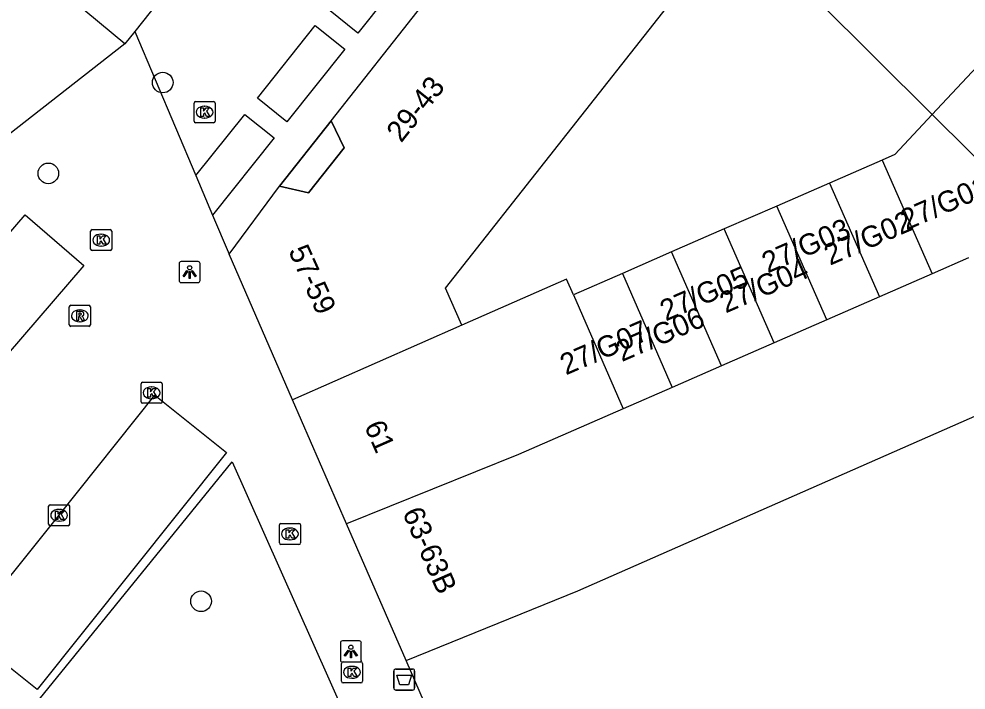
# Model space of a CAD drawing. Extents: x 161882 to 162509, y 381687 to 382379.
# Drawn here: x 162060.59 to 162105.57, y 382010.81 to 382042.68 of the extents above; entities that cross this region are included whole.
import ezdxf

# ---------------------------------------------------------------- set-up
doc = ezdxf.new("R2010")
doc.units = 0
for name, color, linetype in [('IMGEO_Afvalbak', 7, 'Continuous'), ('IMGEO_Boom', 7, 'Continuous'), ('IMGEO_Kolk', 7, 'Continuous'), ('IMGEO_Lichtpunt', 7, 'Continuous'), ('IMGEO_Muur', 7, 'Continuous'), ('IMGEO_Pand', 7, 'Continuous'), ('IMGEO_Pand_nummerreeks', 7, 'Continuous'), ('IMGEO_Pand_overbouw', 7, 'Continuous'), ('IMGEO_Parkeervlak_open', 7, 'Continuous'), ('IMGEO_Rioolput', 7, 'Continuous'), ('IMGEO_Voetpad_open', 7, 'Continuous')]:
    doc.layers.add(name, color=color, linetype=linetype)

msp = doc.modelspace()

# ---------------------------------------------------------------- linework, layer by layer
at = {"layer": 'IMGEO_Afvalbak'}
for p, q in [((162078.395, 382010.911), (162078.395, 382011.711)), ((162078.395, 382011.711), (162078.395, 382010.911)), ((162078.495, 382011.811), (162079.285, 382011.811)), ((162079.285, 382011.811), (162078.495, 382011.811)), ((162079.385, 382011.711), (162079.385, 382010.911)), ((162079.385, 382010.911), (162079.385, 382011.711)), ((162079.285, 382010.811), (162078.495, 382010.811)), ((162078.495, 382010.811), (162079.285, 382010.811))]:
    msp.add_line(p, q, dxfattribs=at)
msp.add_lwpolyline([(162078.538, 382011.525), (162079.242, 382011.525), (162079.093, 382011.055), (162078.687, 382011.055), (162078.538, 382011.525)], dxfattribs=at)
for centre, start, end in [((162078.495, 382011.711), 90, 180), ((162078.495, 382011.711), 90, 180), ((162079.285, 382011.711), 0, 90), ((162079.285, 382011.711), 360, 90), ((162078.495, 382010.911), 180, 270), ((162078.495, 382010.911), 180, 270), ((162079.285, 382010.911), 270, 0), ((162079.285, 382010.911), 270, 0)]:
    msp.add_arc(centre, 0.1, start, end, dxfattribs=at)
at = {"layer": 'IMGEO_Boom'}
for centre in [(162067.42, 382039.66), (162061.986, 382035.347), (162069.241, 382015.027)]:
    msp.add_circle(centre, 0.489, dxfattribs=at)
at = {"layer": 'IMGEO_Kolk'}
for p, q in [((162068.907, 382037.829), (162068.907, 382038.681)), ((162068.982, 382038.755), (162069.834, 382038.755)), ((162069.395, 382038.535), (162069.42, 382038.535)), ((162069.908, 382038.681), (162069.908, 382037.829)), ((162069.418, 382037.975), (162069.393, 382037.975)), ((162069.834, 382037.755), (162068.982, 382037.755)), ((162063.995, 382031.752), (162063.995, 382032.604)), ((162064.07, 382032.678), (162064.922, 382032.678)), ((162064.996, 382032.604), (162064.996, 382031.752)), ((162064.483, 382032.458), (162064.508, 382032.458)), ((162064.922, 382031.678), (162064.07, 382031.678)), ((162064.506, 382031.898), (162064.481, 382031.898)), ((162066.465, 382025.428), (162067.317, 382025.428)), ((162066.39, 382024.502), (162066.39, 382025.354)), ((162066.878, 382025.208), (162066.903, 382025.208)), ((162067.391, 382025.354), (162067.391, 382024.502)), ((162066.901, 382024.648), (162066.876, 382024.648)), ((162067.317, 382024.428), (162066.465, 382024.428)), ((162061.998, 382018.686), (162061.998, 382019.538)), ((162062.073, 382019.612), (162062.925, 382019.612)), ((162062.999, 382019.538), (162062.999, 382018.686)), ((162062.486, 382019.392), (162062.511, 382019.392)), ((162062.509, 382018.832), (162062.484, 382018.832)), ((162072.96, 382017.799), (162072.96, 382018.651)), ((162073.035, 382018.725), (162073.887, 382018.725)), ((162073.961, 382018.651), (162073.961, 382017.799)), ((162062.925, 382018.612), (162062.073, 382018.612)), ((162073.448, 382018.505), (162073.473, 382018.505)), ((162073.471, 382017.945), (162073.446, 382017.945)), ((162073.887, 382017.725), (162073.035, 382017.725)), ((162075.907, 382011.228), (162075.907, 382012.08)), ((162075.982, 382012.154), (162076.834, 382012.154)), ((162076.395, 382011.934), (162076.42, 382011.934)), ((162076.908, 382012.08), (162076.908, 382011.228)), ((162076.834, 382011.154), (162075.982, 382011.154)), ((162076.418, 382011.374), (162076.393, 382011.374))]:
    msp.add_line(p, q, dxfattribs=at)
for points in [[(162068.907, 382037.829), (162068.907, 382038.681)], [(162068.982, 382038.755), (162069.834, 382038.755)], [(162069.228, 382038.455), (162069.351, 382038.455), (162069.351, 382038.304), (162069.481, 382038.455), (162069.645, 382038.455), (162069.499, 382038.304), (162069.652, 382038.055), (162069.5, 382038.055), (162069.415, 382038.219), (162069.351, 382038.152), (162069.351, 382038.055), (162069.228, 382038.055), (162069.228, 382038.455)], [(162069.908, 382038.681), (162069.908, 382037.829)], [(162069.834, 382037.755), (162068.982, 382037.755)], [(162063.995, 382031.752), (162063.995, 382032.604)], [(162064.07, 382032.678), (162064.922, 382032.678)], [(162064.996, 382032.604), (162064.996, 382031.752)], [(162064.316, 382032.378), (162064.439, 382032.378), (162064.439, 382032.227), (162064.569, 382032.378), (162064.733, 382032.378), (162064.587, 382032.227), (162064.74, 382031.978), (162064.588, 382031.978), (162064.503, 382032.142), (162064.439, 382032.075), (162064.439, 382031.978), (162064.316, 382031.978), (162064.316, 382032.378)], [(162064.922, 382031.678), (162064.07, 382031.678)], [(162066.465, 382025.428), (162067.317, 382025.428)], [(162066.39, 382024.502), (162066.39, 382025.354)], [(162066.711, 382025.128), (162066.834, 382025.128), (162066.834, 382024.977), (162066.964, 382025.128), (162067.128, 382025.128), (162066.982, 382024.977), (162067.135, 382024.728), (162066.983, 382024.728), (162066.898, 382024.892), (162066.834, 382024.825), (162066.834, 382024.728), (162066.711, 382024.728), (162066.711, 382025.128)], [(162067.391, 382025.354), (162067.391, 382024.502)], [(162067.317, 382024.428), (162066.465, 382024.428)], [(162061.998, 382018.686), (162061.998, 382019.538)], [(162062.073, 382019.612), (162062.925, 382019.612)], [(162062.999, 382019.538), (162062.999, 382018.686)], [(162062.319, 382019.312), (162062.442, 382019.312), (162062.442, 382019.161), (162062.572, 382019.312), (162062.736, 382019.312), (162062.59, 382019.161), (162062.743, 382018.912), (162062.591, 382018.912), (162062.506, 382019.076), (162062.442, 382019.009), (162062.442, 382018.912), (162062.319, 382018.912), (162062.319, 382019.312)], [(162072.96, 382017.799), (162072.96, 382018.651)], [(162073.035, 382018.725), (162073.887, 382018.725)], [(162073.961, 382018.651), (162073.961, 382017.799)], [(162062.925, 382018.612), (162062.073, 382018.612)], [(162073.281, 382018.425), (162073.404, 382018.425), (162073.404, 382018.274), (162073.534, 382018.425), (162073.698, 382018.425), (162073.552, 382018.274), (162073.705, 382018.025), (162073.553, 382018.025), (162073.468, 382018.189), (162073.404, 382018.122), (162073.404, 382018.025), (162073.281, 382018.025), (162073.281, 382018.425)], [(162073.887, 382017.725), (162073.035, 382017.725)], [(162075.907, 382011.228), (162075.907, 382012.08)], [(162075.982, 382012.154), (162076.834, 382012.154)], [(162076.908, 382012.08), (162076.908, 382011.228)], [(162076.228, 382011.854), (162076.351, 382011.854), (162076.351, 382011.703), (162076.481, 382011.854), (162076.645, 382011.854), (162076.499, 382011.703), (162076.652, 382011.454), (162076.5, 382011.454), (162076.415, 382011.618), (162076.351, 382011.551), (162076.351, 382011.454), (162076.228, 382011.454), (162076.228, 382011.854)], [(162076.834, 382011.154), (162075.982, 382011.154)]]:
    msp.add_lwpolyline(points, dxfattribs=at)
for centre, start, end in [((162068.984, 382038.679), 91.552, 178.448), ((162068.984, 382038.679), 91.552, 178.448), ((162069.832, 382038.679), 1.552, 88.448), ((162069.832, 382038.679), 1.552, 88.448), ((162068.984, 382037.831), 181.552, 268.448), ((162068.984, 382037.831), 181.552, 268.448), ((162069.832, 382037.831), 271.552, 358.448), ((162069.832, 382037.831), 271.552, 358.448), ((162064.072, 382032.602), 91.552, 178.448), ((162064.072, 382032.602), 91.552, 178.448), ((162064.92, 382032.602), 1.552, 88.448), ((162064.92, 382032.602), 1.552, 88.448), ((162064.072, 382031.754), 181.552, 268.448), ((162064.072, 382031.754), 181.552, 268.448), ((162064.92, 382031.754), 271.552, 358.448), ((162064.92, 382031.754), 271.552, 358.448), ((162066.467, 382025.352), 91.552, 178.448), ((162066.467, 382025.352), 91.552, 178.448), ((162067.315, 382025.352), 1.552, 88.448), ((162067.315, 382025.352), 1.552, 88.448), ((162066.467, 382024.504), 181.552, 268.448), ((162066.467, 382024.504), 181.552, 268.448), ((162067.315, 382024.504), 271.552, 358.448), ((162067.315, 382024.504), 271.552, 358.448), ((162062.075, 382019.536), 91.552, 178.448), ((162062.075, 382019.536), 91.552, 178.448), ((162062.923, 382019.536), 1.552, 88.448), ((162062.923, 382019.536), 1.552, 88.448), ((162062.075, 382018.688), 181.552, 268.448), ((162062.075, 382018.688), 181.552, 268.448), ((162062.923, 382018.688), 271.552, 358.448), ((162062.923, 382018.688), 271.552, 358.448), ((162073.037, 382018.649), 91.552, 178.448), ((162073.037, 382018.649), 91.552, 178.448), ((162073.885, 382018.649), 1.552, 88.448), ((162073.885, 382018.649), 1.552, 88.448), ((162073.037, 382017.801), 181.552, 268.448), ((162073.037, 382017.801), 181.552, 268.448), ((162073.885, 382017.801), 271.552, 358.448), ((162073.885, 382017.801), 271.552, 358.448), ((162075.984, 382012.078), 91.552, 178.448), ((162075.984, 382012.078), 91.552, 178.448), ((162076.832, 382012.078), 1.552, 88.448), ((162076.832, 382012.078), 1.552, 88.448), ((162075.984, 382011.23), 181.552, 268.448), ((162075.984, 382011.23), 181.552, 268.448), ((162076.832, 382011.23), 271.552, 358.448), ((162076.832, 382011.23), 271.552, 358.448)]:
    msp.add_arc(centre, 0.0765, start, end, dxfattribs=at)
for centre, major_axis, ratio, start_param, end_param in [((162069.394, 382038.255), (-0.387, 0.002), 0.722429, 4.712389, 7.853982), ((162069.419, 382038.255), (-0.39, 0.002), 0.717154, 1.570796, 4.712389), ((162064.482, 382032.178), (-0.387, 0.002), 0.722429, 4.712389, 7.853982), ((162064.507, 382032.178), (-0.39, 0.002), 0.717154, 1.570796, 4.712389), ((162066.877, 382024.928), (-0.387, 0.002), 0.722429, 4.712389, 7.853982), ((162066.902, 382024.928), (-0.39, 0.002), 0.717154, 1.570796, 4.712389), ((162062.485, 382019.112), (-0.387, 0.002), 0.722429, 4.712389, 7.853982), ((162062.51, 382019.112), (-0.39, 0.002), 0.717154, 1.570796, 4.712389), ((162073.447, 382018.225), (-0.387, 0.002), 0.722429, 4.712389, 7.853982), ((162073.472, 382018.225), (-0.39, 0.002), 0.717154, 1.570796, 4.712389), ((162076.394, 382011.654), (-0.387, 0.002), 0.722429, 4.712389, 7.853982), ((162076.419, 382011.654), (-0.39, 0.002), 0.717154, 1.570796, 4.712389)]:
    msp.add_ellipse(centre, major_axis=major_axis, ratio=ratio, start_param=start_param, end_param=end_param, dxfattribs=at)
at = {"layer": 'IMGEO_Lichtpunt'}
for p, q in [((162068.197, 382031.066), (162068.197, 382030.259)), ((162068.197, 382031.066), (162068.197, 382030.259)), ((162069.099, 382031.161), (162068.291, 382031.161)), ((162069.099, 382031.161), (162068.291, 382031.161)), ((162069.193, 382030.259), (162069.193, 382031.066)), ((162069.193, 382030.259), (162069.193, 382031.066)), ((162068.291, 382030.165), (162069.099, 382030.165)), ((162068.291, 382030.165), (162069.099, 382030.165)), ((162075.856, 382013.048), (162075.856, 382012.241)), ((162075.856, 382013.048), (162075.856, 382012.241)), ((162076.758, 382013.143), (162075.95, 382013.143)), ((162076.758, 382013.143), (162075.95, 382013.143)), ((162076.852, 382012.241), (162076.852, 382013.048)), ((162076.852, 382012.241), (162076.852, 382013.048)), ((162075.95, 382012.147), (162076.758, 382012.147)), ((162075.95, 382012.147), (162076.758, 382012.147))]:
    msp.add_line(p, q, dxfattribs=at)
for points in [[(162068.571, 382030.73), (162068.61, 382030.702), (162068.422, 382030.44), (162068.384, 382030.467), (162068.571, 382030.73)], [(162068.673, 382030.682), (162068.72, 382030.682), (162068.72, 382030.36), (162068.673, 382030.36), (162068.673, 382030.682)], [(162068.783, 382030.702), (162068.821, 382030.729), (162069.008, 382030.467), (162068.969, 382030.439), (162068.783, 382030.702)], [(162076.23, 382012.712), (162076.269, 382012.684), (162076.081, 382012.422), (162076.043, 382012.449), (162076.23, 382012.712)], [(162076.332, 382012.664), (162076.379, 382012.664), (162076.379, 382012.342), (162076.332, 382012.342), (162076.332, 382012.664)], [(162076.442, 382012.684), (162076.48, 382012.711), (162076.667, 382012.449), (162076.628, 382012.421), (162076.442, 382012.684)]]:
    msp.add_lwpolyline(points, dxfattribs=at)
for centre in [(162068.696, 382030.864), (162076.355, 382012.846)]:
    msp.add_circle(centre, 0.0994, dxfattribs=at)
for centre, start, end in [((162068.291, 382031.066), 90, 180), ((162068.291, 382031.066), 90, 180), ((162069.099, 382031.066), 0, 90), ((162069.099, 382031.066), 0, 90), ((162068.291, 382030.259), 180, 270), ((162068.291, 382030.259), 180, 270), ((162069.099, 382030.259), 270, 0), ((162069.099, 382030.259), 270, 360), ((162075.95, 382013.048), 90, 180), ((162075.95, 382013.048), 90, 180), ((162076.758, 382013.048), 0, 90), ((162076.758, 382013.048), 0, 90), ((162075.95, 382012.241), 180, 270), ((162075.95, 382012.241), 180, 270), ((162076.758, 382012.241), 270, 0), ((162076.758, 382012.241), 270, 360)]:
    msp.add_arc(centre, 0.0946, start, end, dxfattribs=at)
at = {"layer": 'IMGEO_Muur'}
msp.add_lwpolyline([(162093.049, 382049.003), (162103.972, 382038.147)], dxfattribs=at)
at = {"layer": 'IMGEO_Pand'}
for points in [[(162065.624, 382041.496), (162054.951, 382050.341)], [(162069.304, 382046.153), (162066.089, 382042.085)], [(162081.622, 382028.142), (162080.853, 382029.902), (162091.578, 382043.507), (162089.962, 382044.781), (162090.783, 382045.823)], [(162075.416, 382037.845), (162079.747, 382043.318)], [(162066.089, 382042.085), (162065.624, 382041.496)], [(162103.972, 382038.147), (162107.753, 382042.178), (162112.396, 382037.564), (162111.772, 382036.656), (162112.254, 382036.261)], [(162065.624, 382041.496), (162047.564, 382027.394)], [(162103.972, 382038.147), (162102.186, 382036.243), (162101.589, 382035.982)], [(162109.264, 382032.889), (162103.972, 382038.147)], [(162075.416, 382037.845), (162076.035, 382036.565), (162074.335, 382034.416), (162072.958, 382034.74)], [(162101.589, 382035.982), (162099.082, 382034.888)], [(162101.589, 382035.982), (162103.968, 382030.577)], [(162099.082, 382034.888), (162096.583, 382033.797)], [(162099.082, 382034.888), (162101.461, 382029.482)], [(162070.577, 382031.503), (162072.958, 382034.74)], [(162096.583, 382033.797), (162094.084, 382032.706)], [(162098.962, 382028.391), (162096.583, 382033.797)], [(162094.084, 382032.706), (162091.585, 382031.615)], [(162096.464, 382027.3), (162094.084, 382032.706)], [(162073.588, 382024.593), (162070.577, 382031.503)], [(162091.585, 382031.615), (162089.255, 382030.597)], [(162093.965, 382026.209), (162091.585, 382031.615)], [(162105.694, 382031.331), (162103.968, 382030.577)], [(162089.255, 382030.597), (162086.925, 382029.58)], [(162089.255, 382030.597), (162091.618, 382025.184)], [(162103.968, 382030.577), (162101.461, 382029.482)], [(162086.925, 382029.58), (162086.603, 382030.317), (162081.622, 382028.142)], [(162086.925, 382029.58), (162089.288, 382024.167)], [(162101.461, 382029.482), (162098.962, 382028.391)], [(162081.622, 382028.142), (162073.588, 382024.593)], [(162098.962, 382028.391), (162096.464, 382027.3)], [(162096.464, 382027.3), (162093.965, 382026.209)], [(162093.965, 382026.209), (162091.618, 382025.184)], [(162078.98, 382012.213), (162087.135, 382015.525), (162108.51, 382024.928)], [(162091.618, 382025.184), (162089.288, 382024.167)], [(162076.155, 382018.699), (162073.588, 382024.593)], [(162089.288, 382024.167), (162084.309, 382021.993), (162076.155, 382018.699)], [(162078.98, 382012.213), (162076.155, 382018.699)], [(162081.094, 382007.361), (162078.98, 382012.213)]]:
    msp.add_lwpolyline(points, dxfattribs=at)
at = {"layer": 'IMGEO_Pand_overbouw'}
msp.add_lwpolyline([(162075.416, 382037.845), (162072.958, 382034.74), (162074.335, 382034.416), (162076.035, 382036.565)], close=True, dxfattribs=at)
at = {"layer": 'IMGEO_Parkeervlak_open'}
for points in [[(162093.049, 382049.003), (162103.972, 382038.147)], [(162079.441, 382045.475), (162076.68, 382042.013), (162075.285, 382043.128), (162078.037, 382046.607), (162079.441, 382045.475)], [(162076.074, 382041.241), (162073.317, 382037.797), (162071.919, 382038.914), (162074.663, 382042.368), (162076.074, 382041.241)], [(162068.992, 382035.24), (162071.32, 382038.151), (162072.716, 382037.039), (162069.789, 382033.361)]]:
    msp.add_lwpolyline(points, dxfattribs=at)
at = {"layer": 'IMGEO_Rioolput'}
for p, q in [((162062.981, 382028.158), (162062.981, 382029.01)), ((162063.056, 382029.084), (162063.908, 382029.084)), ((162063.982, 382029.01), (162063.982, 382028.158)), ((162063.469, 382028.864), (162063.494, 382028.864)), ((162063.908, 382028.084), (162063.056, 382028.084)), ((162063.492, 382028.304), (162063.467, 382028.304))]:
    msp.add_line(p, q, dxfattribs=at)
for points in [[(162062.981, 382028.158), (162062.981, 382029.01)], [(162063.056, 382029.084), (162063.908, 382029.084)], [(162063.982, 382029.01), (162063.982, 382028.158)], [(162063.57, 382028.782), (162063.318, 382028.784), (162063.318, 382028.384)], [(162063.318, 382028.384), (162063.442, 382028.384), (162063.442, 382028.546), (162063.453, 382028.546)], [(162063.496, 382028.703), (162063.442, 382028.703), (162063.442, 382028.622)], [(162063.442, 382028.622), (162063.494, 382028.622)], [(162063.908, 382028.084), (162063.056, 382028.084)], [(162063.5, 382028.517), (162063.571, 382028.384), (162063.711, 382028.384), (162063.646, 382028.51)]]:
    msp.add_lwpolyline(points, dxfattribs=at)
for centre, radius, start, end in [((162063.058, 382029.008), 0.0765, 91.552, 178.448), ((162063.058, 382029.008), 0.0765, 91.552, 178.448), ((162063.906, 382029.008), 0.0765, 1.552, 88.448), ((162063.906, 382029.008), 0.0765, 1.552, 88.448), ((162063.452, 382028.493), 0.0533, 26.0293, 88.6989), ((162063.478, 382028.811), 0.19, 274.7715, 282.9687), ((162063.502, 382028.607), 0.0964, 77.0061, 93.1865), ((162063.516, 382028.664), 0.0378, 276.6634, 79.6772), ((162063.569, 382028.672), 0.109, 350.3612, 89.416), ((162063.567, 382028.672), 0.112, 277.5842, 350.9817), ((162063.551, 382028.457), 0.108, 29.5134, 73.7905), ((162063.058, 382028.16), 0.0765, 181.552, 268.448), ((162063.058, 382028.16), 0.0765, 181.552, 268.448), ((162063.906, 382028.16), 0.0765, 271.552, 358.448), ((162063.906, 382028.16), 0.0765, 271.552, 358.448)]:
    msp.add_arc(centre, radius, start, end, dxfattribs=at)
for centre, major_axis, ratio, start_param, end_param in [((162063.468, 382028.584), (-0.387, 0.002), 0.722429, 4.712389, 7.853982), ((162063.493, 382028.584), (-0.39, 0.002), 0.717154, 1.570796, 4.712389)]:
    msp.add_ellipse(centre, major_axis=major_axis, ratio=ratio, start_param=start_param, end_param=end_param, dxfattribs=at)
at = {"layer": 'IMGEO_Voetpad_open'}
for points in [[(162066.089, 382042.085), (162068.992, 382035.24)], [(162072.958, 382034.74), (162075.416, 382037.845)], [(162068.992, 382035.24), (162069.789, 382033.361)], [(162060.879, 382033.384), (162063.675, 382030.976), (162054.138, 382019.903), (162051.342, 382022.311), (162060.879, 382033.384)], [(162069.789, 382033.361), (162070.577, 382031.503)], [(162067.046, 382024.818), (162070.452, 382022.092), (162061.448, 382010.84), (162058.042, 382013.567), (162062.499, 382019.112), (162067.046, 382024.818)], [(162061.341, 382010.107), (162070.724, 382021.65), (162076.855, 382007.857)]]:
    msp.add_lwpolyline(points, dxfattribs=at)

# ---------------------------------------------------------------- texts
at = {"layer": 'IMGEO_Pand_nummerreeks'}
for s, rotation, p in [('29-43', 51.5688, (162078.745, 382036.766)), ('27/G01', 23.434, (162102.737, 382032.627)), ('27/G02', 23.435, (162099.11, 382030.96)), ('27/G03', 23.435, (162096.152, 382030.591)), ('57-59', 294.3818, (162073.371, 382031.67)), ('27/G04', 23.435, (162094.156, 382028.692)), ('27/G05', 23.435, (162091.313, 382028.313)), ('27/G06', 23.435, (162089.226, 382026.384)), ('27/G07', 23.435, (162086.569, 382025.751)), ('61', 293.7274, (162076.975, 382023.348)), ('63-63B', 293.6572, (162078.786, 382019.233))]:
    msp.add_text(s, height=1, rotation=rotation, dxfattribs=at).set_placement(p)

doc.saveas('drawing.dxf')
